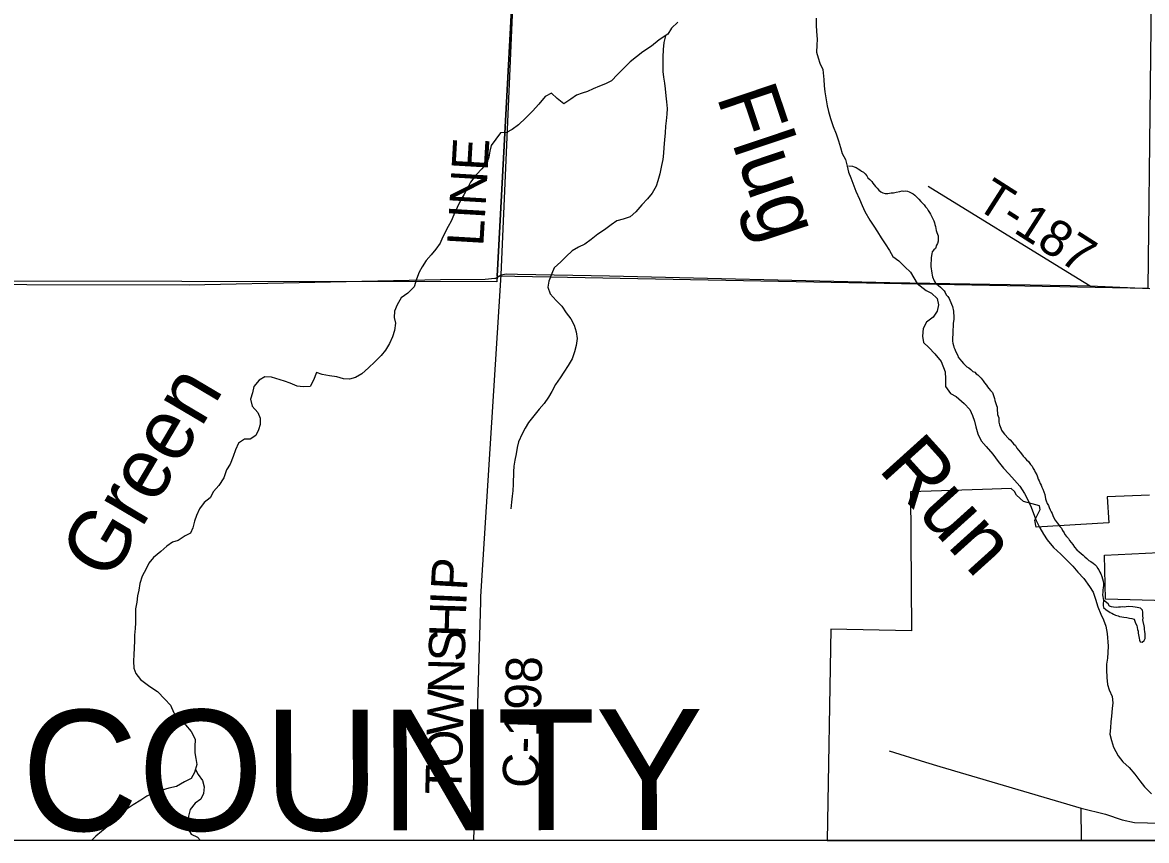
# Model space of a CAD drawing. Extents: x 0 to 34, y 0 to 22.
# Drawn here: x 25.169 to 26.932, y 14.1 to 15.382 of the extents above; entities that cross this region are included whole.
import ezdxf

# ---------------------------------------------------------------- set-up
doc = ezdxf.new("R2010")
doc.units = 0
for name, color, linetype in [('GM_X_City_Street', 7, 'Continuous'), ('GM_X_County_Road', 7, 'Continuous'), ('GM_X_County_Road_Text', 7, 'Continuous'), ('GM_X_County_Text', 7, 'Continuous'), ('GM_X_Minor_Lake', 7, 'Continuous'), ('GM_X_Minor_River', 7, 'Continuous'), ('GM_X_Minor_River_Text', 7, 'Continuous'), ('GM_X_Section', 7, 'Continuous'), ('GM_X_Township_Road', 7, 'Continuous'), ('GM_X_Township_Road_Text', 7, 'Continuous'), ('SH_Data', 7, 'Continuous')]:
    doc.layers.add(name, color=color, linetype=linetype)

msp = doc.modelspace()

# ---------------------------------------------------------------- linework, layer by layer
at = {"layer": 'GM_X_City_Street'}
for p, q in [((26.5286, 14.2404), (26.5854, 14.223)), ((26.8303, 14.1), (26.8294, 14.1507))]:
    msp.add_line(p, q, dxfattribs=at)
for points in [[(26.9369, 14.6413), (26.8704, 14.6389), (26.873, 14.5981), (26.7592, 14.5911), (26.7568, 14.6024), (26.7652, 14.6187), (26.7642, 14.6246), (26.7389, 14.6316), (26.7279, 14.6414), (26.7251, 14.6472), (26.7199, 14.6517), (26.6746, 14.6503), (26.562, 14.6466), (26.5633, 14.4289), (26.4369, 14.4315), (26.4312, 14.1), (27.5103, 14.1)], [(26.9639, 14.4755), (26.8676, 14.4786), (26.8663, 14.5471), (26.9519, 14.5515)], [(26.5854, 14.223), (26.6081, 14.216), (26.8294, 14.1507)], [(26.8294, 14.1507), (26.8679, 14.1413), (26.8936, 14.1326), (26.9134, 14.1281), (26.9539, 14.1274)]]:
    msp.add_lwpolyline(points, dxfattribs=at)
at = {"layer": 'GM_X_County_Road'}
msp.add_line((25.8882, 14.4825), (25.9196, 14.987), dxfattribs=at)
for points in [[(25.9196, 14.987), (25.9448, 15.5625), (25.9647, 16.0268), (25.9746, 16.3822)], [(23.8356, 14.976), (24.1256, 14.9725), (24.4361, 14.9725), (24.6013, 14.9725), (24.9205, 14.9723), (25.4304, 14.971), (25.8247, 14.9796), (25.8949, 14.9801), (25.9099, 14.9816), (25.9117, 14.9818), (25.9196, 14.987)], [(25.9196, 14.987), (25.9277, 14.9881), (25.9453, 14.988), (26.0896, 14.9852), (26.5296, 14.9746), (26.8435, 14.9693), (26.9373, 14.9656)], [(25.8772, 14.1), (25.8877, 14.4745), (25.8882, 14.4825)]]:
    msp.add_lwpolyline(points, dxfattribs=at)
at = {"layer": 'GM_X_Minor_Lake'}
for points in [[(26.8647, 14.4769), (26.8643, 14.4754), (26.8642, 14.472), (26.8638, 14.4686), (26.8645, 14.4651)], [(26.8645, 14.4651), (26.8682, 14.4624), (26.8749, 14.4577), (26.8776, 14.4565), (26.8802, 14.4549), (26.8835, 14.4534), (26.8873, 14.4521), (26.8899, 14.4513), (26.8933, 14.4505), (26.8963, 14.4501), (26.9009, 14.4496), (26.9054, 14.4487), (26.9092, 14.4479), (26.9126, 14.4471), (26.9136, 14.444), (26.9147, 14.4406), (26.9169, 14.4371), (26.9172, 14.4337), (26.9179, 14.431), (26.919, 14.4284), (26.9189, 14.425), (26.9196, 14.4223), (26.9203, 14.417), (26.921, 14.4143), (26.922, 14.4116), (26.9251, 14.4108), (26.9285, 14.4134), (26.9297, 14.4168), (26.9299, 14.424), (26.9296, 14.4274), (26.9289, 14.4308), (26.9289, 14.4339), (26.9282, 14.4365), (26.9269, 14.4434), (26.9265, 14.446), (26.9266, 14.4487), (26.9263, 14.4521), (26.926, 14.4555), (26.926, 14.4582), (26.9257, 14.4609), (26.9228, 14.4643), (26.9175, 14.4652), (26.9141, 14.466), (26.9103, 14.4665), (26.9035, 14.4666), (26.9001, 14.4663), (26.8971, 14.466), (26.8936, 14.4661), (26.891, 14.4657), (26.8883, 14.4658), (26.8857, 14.4655), (26.88, 14.4656), (26.877, 14.4664), (26.874, 14.4676), (26.8718, 14.471), (26.8647, 14.4769)]]:
    msp.add_lwpolyline(points, dxfattribs=at)
at = {"layer": 'GM_X_Minor_River'}
for points in [[(26.1967, 15.3827), (26.1871, 15.3733), (26.1813, 15.3639), (26.1679, 15.3553), (26.1557, 15.3452), (26.1419, 15.3363), (26.132, 15.3288), (26.1224, 15.3205), (26.112, 15.3108), (26.1024, 15.301)], [(26.4141, 15.3891), (26.414, 15.3781), (26.4146, 15.3682), (26.4152, 15.3561), (26.4151, 15.3466), (26.4146, 15.336), (26.4168, 15.3272), (26.4197, 15.3184), (26.4242, 15.3089), (26.4259, 15.2929), (26.4265, 15.2831), (26.4276, 15.2739), (26.429, 15.2641), (26.4311, 15.2519), (26.4333, 15.2428), (26.4366, 15.2321), (26.4406, 15.2191), (26.445, 15.2077), (26.4491, 15.197), (26.452, 15.1864), (26.4549, 15.1768), (26.4601, 15.1677), (26.4623, 15.1574), (26.4648, 15.1475), (26.4681, 15.1387), (26.4729, 15.1265), (26.4759, 15.1178), (26.4818, 15.1056), (26.4859, 15.0957), (26.4903, 15.0861), (26.4981, 15.0727), (26.5041, 15.0632), (26.51, 15.0544), (26.516, 15.0448), (26.5223, 15.0353), (26.5287, 15.025), (26.5343, 15.0154), (26.5433, 15.0085), (26.553, 14.9993), (26.5617, 14.9912), (26.5725, 14.9732), (26.5864, 14.9621), (26.595, 14.9582), (26.6037, 14.9497), (26.6055, 14.9395), (26.6035, 14.93), (26.5973, 14.9202), (26.5869, 14.9127), (26.5815, 14.9025), (26.5806, 14.8908), (26.582, 14.8809), (26.5907, 14.8728), (26.6, 14.8628), (26.6098, 14.851), (26.616, 14.8346), (26.6167, 14.8239), (26.6169, 14.8118), (26.6247, 14.8007), (26.6334, 14.7961), (26.6462, 14.7853), (26.6548, 14.7757), (26.6589, 14.7662), (26.6622, 14.7574), (26.6644, 14.7483), (26.6673, 14.7376), (26.6728, 14.7265), (26.6807, 14.7177), (26.6912, 14.7058), (26.6994, 14.694), (26.7076, 14.6836), (26.7159, 14.6748), (26.7249, 14.6649), (26.7335, 14.6553), (26.7409, 14.6442), (26.7461, 14.6343), (26.7513, 14.6224), (26.7546, 14.6129), (26.7587, 14.6018), (26.7646, 14.59), (26.7702, 14.5805), (26.7761, 14.5713), (26.7859, 14.5594), (26.7975, 14.5487), (26.8076, 14.5391), (26.8162, 14.5299)], [(26.1777, 15.3616), (26.1751, 15.3511), (26.1738, 15.3401), (26.1733, 15.3279), (26.1732, 15.3162), (26.1734, 15.3055), (26.1745, 15.2968), (26.1759, 15.2873), (26.1769, 15.2786), (26.1783, 15.2675), (26.1793, 15.258), (26.18, 15.2474), (26.1795, 15.2387), (26.1786, 15.2284), (26.1777, 15.2197), (26.1769, 15.2095), (26.176, 15.1985), (26.1751, 15.1863), (26.1746, 15.1776), (26.1734, 15.1674), (26.1714, 15.1583), (26.1686, 15.145), (26.1658, 15.1344), (26.163, 15.1257), (26.1565, 15.1148), (26.1491, 15.1061), (26.1407, 15.0964), (26.1311, 15.0858), (26.1219, 15.0776), (26.1112, 15.0739), (26.101, 15.0713), (26.0922, 15.065), (26.0818, 15.0575), (26.0715, 15.0504), (26.0608, 15.0422), (26.0509, 15.0351), (26.0409, 15.0302), (26.0314, 15.0246), (26.0218, 15.0156), (26.0134, 15.007), (26.003, 14.9976), (25.9995, 14.9889), (25.9948, 14.9768), (25.9932, 14.9674), (25.9969, 14.9571), (26.0059, 14.9467), (26.0152, 14.9375), (26.0219, 14.9272), (26.029, 14.918), (26.0342, 14.9081), (26.0375, 14.8974), (26.0389, 14.8868), (26.0373, 14.8758), (26.0349, 14.8659), (26.0314, 14.855), (26.0248, 14.8448), (26.0182, 14.8342), (26.0124, 14.8252), (26.0051, 14.815), (25.9993, 14.8041), (25.9943, 14.795), (25.9873, 14.7852), (25.9796, 14.7762), (25.9627, 14.7555), (25.9573, 14.7464), (25.9526, 14.7374), (25.9472, 14.7249), (25.9448, 14.7162), (25.9432, 14.706), (25.9412, 14.6961), (25.9399, 14.687), (25.9391, 14.6779), (25.9389, 14.6586), (25.938, 14.6483), (25.9371, 14.6396), (25.9363, 14.6305), (25.935, 14.6199)], [(26.1024, 15.301), (26.0928, 15.2908), (26.0833, 15.2864), (26.0742, 15.2827), (26.0642, 15.2783), (26.0555, 15.2742), (26.0467, 15.2716), (26.038, 15.2687), (26.0292, 15.2623), (26.0181, 15.2548), (26.0076, 15.2633), (25.9989, 15.2717), (25.9886, 15.2665), (25.979, 15.2545), (25.969, 15.2432), (25.9583, 15.2327), (25.9472, 15.2222), (25.9372, 15.2147), (25.9284, 15.2099), (25.9186, 15.2092), (25.9039, 15.1896), (25.9023, 15.1805), (25.9003, 15.1711), (25.8972, 15.1624), (25.8895, 15.153), (25.8814, 15.1439), (25.8718, 15.1323), (25.8675, 15.1236), (25.8613, 15.1123), (25.8559, 15.1032), (25.8509, 15.0926), (25.8458, 15.0809), (25.8415, 15.0711), (25.8365, 15.0624), (25.8279, 15.0451), (25.824, 15.0364), (25.8175, 15.027), (25.8102, 15.0179), (25.8021, 15.0093), (25.7959, 14.9995), (25.7913, 14.9908), (25.787, 14.9798), (25.7834, 14.9681), (25.7735, 14.9583), (25.7628, 14.9505), (25.7566, 14.9399), (25.7523, 14.9297), (25.7522, 14.9199), (25.754, 14.9111), (25.7527, 14.8993), (25.7495, 14.8895), (25.7445, 14.8789), (25.7383, 14.8688), (25.7314, 14.8601), (25.7218, 14.8503), (25.7118, 14.8409), (25.7011, 14.8316), (25.6915, 14.8256), (25.682, 14.823), (25.6726, 14.8235), (25.662, 14.8271), (25.6506, 14.8283), (25.6389, 14.8307), (25.6302, 14.8339), (25.6255, 14.8218), (25.6201, 14.8116), (25.6095, 14.8113), (25.6, 14.8125), (25.5887, 14.8172), (25.58, 14.82), (25.5596, 14.8263), (25.5489, 14.8271), (25.5402, 14.8215), (25.5321, 14.8117), (25.5297, 14.8019), (25.5269, 14.7921), (25.5291, 14.7807), (25.5381, 14.7711), (25.5418, 14.7623), (25.542, 14.7524), (25.5393, 14.7437), (25.535, 14.735), (25.5262, 14.7294), (25.5171, 14.7292), (25.5079, 14.7228), (25.5033, 14.7122), (25.4997, 14.702), (25.4947, 14.6899), (25.4892, 14.6809), (25.4846, 14.6688), (25.4772, 14.6567), (25.4688, 14.6469), (25.4633, 14.6371), (25.4542, 14.63), (25.4465, 14.6202), (25.4422, 14.6096), (25.439, 14.6005), (25.4363, 14.5903), (25.4327, 14.5816), (25.424, 14.5776), (25.4133, 14.5705)], [(26.4647, 15.1575), (26.4708, 15.1574), (26.4734, 15.1562), (26.4764, 15.155), (26.4798, 15.153), (26.4824, 15.1515), (26.485, 15.1495), (26.488, 15.1476), (26.4906, 15.1452), (26.4932, 15.1418), (26.495, 15.1391), (26.498, 15.136), (26.501, 15.1333), (26.5028, 15.1306), (26.505, 15.1279), (26.5068, 15.1252), (26.5098, 15.1225), (26.5124, 15.1194), (26.5154, 15.1167), (26.5184, 15.1151), (26.5221, 15.1142), (26.5263, 15.1145), (26.5316, 15.1152), (26.5354, 15.1155), (26.5392, 15.1162), (26.5453, 15.1176), (26.5487, 15.1183), (26.5514, 15.1182), (26.5544, 15.1185), (26.557, 15.1181), (26.5597, 15.1169), (26.563, 15.1153), (26.566, 15.1137), (26.5686, 15.1118), (26.572, 15.1083), (26.5749, 15.1056), (26.5783, 15.1017), (26.5809, 15.099), (26.5835, 15.0967), (26.5853, 15.0936), (26.5879, 15.0909), (26.5893, 15.0879), (26.5915, 15.0844), (26.593, 15.0817), (26.5985, 15.0714), (26.5995, 15.0683), (26.6002, 15.0656), (26.6009, 15.0626), (26.6016, 15.0592), (26.6019, 15.0565), (26.6034, 15.0531), (26.6041, 15.0504), (26.6052, 15.0477), (26.6051, 15.0451), (26.6054, 15.0424), (26.605, 15.0397), (26.6042, 15.036), (26.6026, 15.0333), (26.601, 15.0281), (26.5983, 15.0262), (26.5959, 15.0229), (26.5951, 15.0195), (26.5942, 15.0142), (26.5941, 15.0085), (26.5937, 15.0054), (26.5936, 15.0001), (26.5943, 14.9963), (26.5946, 14.9929), (26.5952, 14.9895), (26.5956, 14.9861), (26.5966, 14.9834), (26.5988, 14.9773), (26.6006, 14.9746), (26.6032, 14.9723), (26.6058, 14.9703), (26.6088, 14.9676), (26.6144, 14.9618), (26.6162, 14.9591), (26.618, 14.9556), (26.6206, 14.9529), (26.6224, 14.9499), (26.6235, 14.9472), (26.6278, 14.9369), (26.6292, 14.93), (26.6295, 14.9266), (26.6298, 14.9228), (26.6297, 14.9167), (26.6293, 14.9141), (26.6288, 14.9107), (26.6287, 14.905), (26.6282, 14.9016), (26.6282, 14.8989), (26.6279, 14.8826), (26.6282, 14.8796), (26.6292, 14.8761), (26.6299, 14.8735), (26.6314, 14.87), (26.6325, 14.8673), (26.6361, 14.8604), (26.6368, 14.8578), (26.639, 14.8547)], [(26.639, 14.8547), (26.6416, 14.8516), (26.6449, 14.8477), (26.6475, 14.8454), (26.6501, 14.8427), (26.6531, 14.8408), (26.6565, 14.8384), (26.6598, 14.8353), (26.6628, 14.8341), (26.665, 14.8314), (26.6676, 14.8298), (26.6702, 14.8275), (26.6728, 14.8248), (26.6758, 14.8206), (26.678, 14.8175), (26.6809, 14.814), (26.6828, 14.8113), (26.6846, 14.8086), (26.6872, 14.8055), (26.6902, 14.8021), (26.6934, 14.7929), (26.6941, 14.7899), (26.6955, 14.7849), (26.6969, 14.7818), (26.698, 14.7792), (26.6979, 14.7735), (26.6982, 14.7708), (26.6985, 14.7678), (26.6996, 14.7651), (26.7003, 14.7624), (26.7002, 14.759), (26.7005, 14.7556), (26.7016, 14.7518), (26.7034, 14.7464), (26.7048, 14.7434), (26.707, 14.7395), (26.7092, 14.7368), (26.7155, 14.7302), (26.7181, 14.7279), (26.7211, 14.7244), (26.7233, 14.7217), (26.7263, 14.719), (26.7285, 14.7152), (26.7336, 14.709), (26.7362, 14.7063), (26.7384, 14.7025), (26.7414, 14.7001), (26.7436, 14.6967), (26.747, 14.694), (26.7503, 14.6897), (26.7525, 14.6866), (26.7543, 14.6832), (26.7565, 14.6801), (26.7576, 14.6774), (26.7598, 14.6732), (26.7609, 14.6702), (26.7623, 14.6667), (26.7634, 14.664), (26.7652, 14.6598), (26.7666, 14.6568), (26.7677, 14.6541), (26.7692, 14.651), (26.771, 14.6464), (26.7724, 14.6426), (26.7738, 14.6358), (26.7748, 14.6323), (26.7763, 14.6281), (26.7781, 14.625), (26.7792, 14.622), (26.781, 14.6182), (26.7824, 14.6155), (26.7839, 14.6128), (26.785, 14.6097), (26.7868, 14.6059), (26.789, 14.6021), (26.7919, 14.5982), (26.7941, 14.5955), (26.796, 14.5924), (26.7985, 14.5894), (26.8004, 14.5859), (26.8026, 14.5824), (26.804, 14.5798), (26.8066, 14.5767), (26.8096, 14.5732), (26.811, 14.5705), (26.8136, 14.5674), (26.8162, 14.564), (26.8191, 14.5597), (26.8228, 14.5555), (26.8265, 14.5524), (26.8295, 14.55), (26.8329, 14.5473), (26.8355, 14.5446), (26.8385, 14.5423), (26.8418, 14.5392), (26.8448, 14.5372), (26.8481, 14.5349), (26.8511, 14.5329), (26.8541, 14.5294), (26.8552, 14.5268), (26.857, 14.5241)], [(25.4133, 14.5705), (25.4045, 14.5675), (25.3957, 14.5615), (25.3858, 14.5533), (25.3747, 14.5439), (25.367, 14.5349), (25.3631, 14.5258), (25.3569, 14.5145), (25.3533, 14.5031), (25.3517, 14.4922), (25.3497, 14.4834), (25.3484, 14.4736), (25.3464, 14.463), (25.3462, 14.441), (25.3457, 14.4322), (25.3448, 14.422), (25.3447, 14.4133), (25.3442, 14.4015), (25.3437, 14.3916), (25.3432, 14.381), (25.3439, 14.3704), (25.3468, 14.3616), (25.3543, 14.3524), (25.3689, 14.3413), (25.381, 14.3335), (25.3922, 14.3217), (25.4012, 14.3121), (25.4064, 14.3002), (25.4158, 14.2903), (25.4248, 14.2811), (25.4338, 14.2707), (25.4397, 14.2589), (25.4392, 14.2467), (25.4395, 14.2372), (25.4412, 14.2285), (25.4423, 14.219), (25.4391, 14.2065), (25.4337, 14.1971), (25.4234, 14.1919), (25.4108, 14.1848), (25.3986, 14.1819), (25.3868, 14.1786), (25.3746, 14.1742), (25.3643, 14.1697), (25.3548, 14.1634), (25.3426, 14.1559), (25.333, 14.1499), (25.3242, 14.1421), (25.3138, 14.1319), (25.3043, 14.1233), (25.2932, 14.1139), (25.2843, 14.1068), (25.2771, 14.1)], [(26.8162, 14.5299), (26.8245, 14.5207), (26.8339, 14.5107), (26.8424, 14.4984), (26.8484, 14.4893), (26.8521, 14.4786), (26.8557, 14.4664), (26.8605, 14.455), (26.8646, 14.4458), (26.8683, 14.4359), (26.8704, 14.4245), (26.8717, 14.4047), (26.8716, 14.3945), (26.8707, 14.3858), (26.8691, 14.3763), (26.869, 14.3676), (26.8696, 14.3558), (26.871, 14.3448), (26.8732, 14.336), (26.878, 14.3257), (26.8791, 14.3158), (26.8782, 14.3067), (26.8773, 14.295), (26.8761, 14.2863), (26.8756, 14.2768), (26.8747, 14.2665), (26.8772, 14.2566), (26.8802, 14.2463), (26.8876, 14.233), (26.8951, 14.2234), (26.9048, 14.2142), (26.9138, 14.2038), (26.9217, 14.1935), (26.9291, 14.1839), (26.94, 14.1732)], [(26.857, 14.5241), (26.8588, 14.5206), (26.8603, 14.5179), (26.8621, 14.5137), (26.8638, 14.5065), (26.8645, 14.5023), (26.8648, 14.4996), (26.864, 14.4962), (26.8636, 14.4932), (26.8635, 14.4894), (26.863, 14.4849), (26.8644, 14.4769)], [(25.4404, 14.2114), (25.4448, 14.2034), (25.4515, 14.1942), (25.454, 14.1843), (25.4531, 14.1737), (25.4489, 14.1646), (25.4401, 14.1583), (25.432, 14.1485), (25.4296, 14.1383), (25.4284, 14.1296), (25.4279, 14.1201), (25.4335, 14.1098), (25.4436, 14.1051), (25.448, 14.1)]]:
    msp.add_lwpolyline(points, dxfattribs=at)
at = {"layer": 'GM_X_Section'}
for points in [[(26.945, 15.9224), (26.9342, 14.9655), (25.9137, 14.9847), (25.9617, 15.8807), (25.9635, 15.9304)], [(25.9617, 15.8807), (25.9137, 14.9847), (25.9129, 14.9756), (24.9245, 14.9768), (24.9186, 15.4351), (24.894, 15.7536), (24.8984, 15.9127)]]:
    msp.add_lwpolyline(points, close=True, dxfattribs=at)
at = {"layer": 'GM_X_Township_Road'}
msp.add_lwpolyline([(26.5895, 15.126), (26.8087, 14.9911), (26.8435, 14.9693)], dxfattribs=at)
at = {"layer": 'SH_Data'}
msp.add_lwpolyline([(23.5167, 20.9), (30.3167, 20.9), (30.3167, 14.1), (23.5167, 14.1)], close=True, dxfattribs=at)

# ---------------------------------------------------------------- texts
at = {"layer": 'GM_X_County_Road_Text'}
for s, height, rotation, p in [('LINE', 0.05682, 86.6697, (25.8917, 15.0308)), ('P', 0.0568, 86.7578, (25.8661, 14.4911)), ('I', 0.0568, 87.5716, (25.8651, 14.468)), ('H', 0.0568, 88.2803, (25.8636, 14.4182)), ('S', 0.0568, 88.5833, (25.8627, 14.38)), ('N', 0.0568, 88.5828, (25.8614, 14.33)), ('C-198', 0.05682, 88.3475, (25.9785, 14.1816)), ('W', 0.0568, 88.5833, (25.8598, 14.2642)), ('O', 0.0568, 88.5828, (25.8586, 14.2142)), ('T', 0.0568, 88.5856, (25.8575, 14.1717))]:
    msp.add_text(s, height=height, rotation=rotation, dxfattribs=at).set_placement(p)
at = {"layer": 'GM_X_County_Text'}
msp.add_text('SANDUSKY COUNTY', height=0.189394, rotation=0.0833, dxfattribs=at).set_placement((23.7039, 14.1129))
at = {"layer": 'GM_X_Minor_River_Text'}
for s, height, rotation, p in [('Flug', 0.09476, 288.5487, (26.2572, 15.2666)), ('Green', 0.09475, 59.3515, (25.3056, 14.5036)), ('Run', 0.09476, 312.0477, (26.5096, 14.6816))]:
    msp.add_text(s, height=height, rotation=rotation, dxfattribs=at).set_placement(p)
at = {"layer": 'GM_X_Township_Road_Text'}
msp.add_text('T-187', height=0.05682, rotation=327.3955, dxfattribs=at).set_placement((26.6613, 15.0931))

doc.saveas('drawing.dxf')
